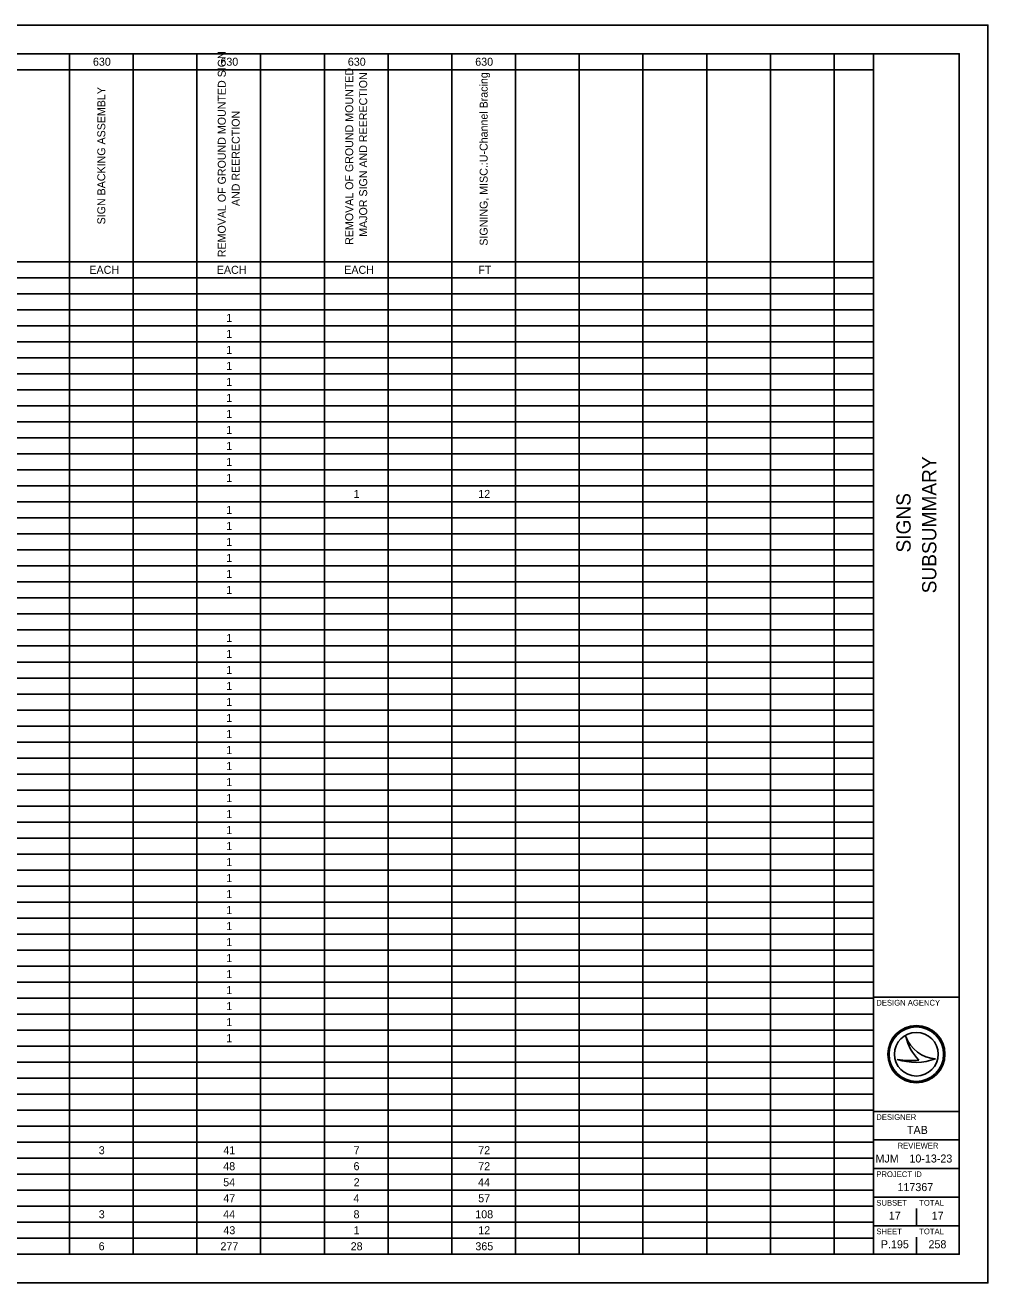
# Model space of a CAD drawing. Extents: x 0 to 34, y 0 to 22.
# Drawn here: x 17.16 to 34, y 0 to 22 of the extents above; entities that cross this region are included whole.
import ezdxf

# ---------------------------------------------------------------- set-up
doc = ezdxf.new("R2010")
doc.units = 0
for name, color, linetype in [('Default', 7, 'Continuous'), ('SH_Border', 7, 'Continuous'), ('SH_Cut_Line', 7, 'Continuous'), ('SH_Data', 7, 'Continuous')]:
    doc.layers.add(name, color=color, linetype=linetype)

msp = doc.modelspace()

# ---------------------------------------------------------------- linework, layer by layer
at = {"layer": 'Default'}
for p, q in [((1.5, 21.5), (32, 21.5)), ((17.938, 21.5), (17.938, 0.5)), ((19.053, 21.5), (19.053, 0.5)), ((20.167, 21.5), (20.167, 0.5)), ((21.282, 21.5), (21.282, 0.5)), ((22.396, 21.5), (22.396, 0.5)), ((23.51, 21.5), (23.51, 0.5)), ((24.625, 21.5), (24.625, 0.5)), ((25.739, 21.5), (25.739, 0.5)), ((26.854, 21.5), (26.854, 0.5)), ((27.968, 21.5), (27.968, 0.5)), ((29.083, 21.5), (29.083, 0.5)), ((30.197, 21.5), (30.197, 0.5)), ((31.312, 21.5), (31.312, 0.5)), ((32, 21.5), (32, 0.5)), ((8.646, 21.22), (32, 21.22)), ((8.646, 17.86), (32, 17.86)), ((1.5, 17.58), (32, 17.58)), ((1.5, 17.3), (32, 17.3)), ((1.5, 17.02), (32, 17.02)), ((1.5, 16.74), (32, 16.74)), ((1.5, 16.46), (32, 16.46)), ((1.5, 16.18), (32, 16.18)), ((1.5, 15.9), (32, 15.9)), ((1.5, 15.62), (32, 15.62)), ((1.5, 15.34), (32, 15.34)), ((1.5, 15.06), (32, 15.06)), ((1.5, 14.78), (32, 14.78)), ((1.5, 14.5), (32, 14.5)), ((1.5, 14.22), (32, 14.22)), ((1.5, 13.94), (32, 13.94)), ((1.5, 13.66), (32, 13.66)), ((1.5, 13.38), (32, 13.38)), ((1.5, 13.1), (32, 13.1)), ((1.5, 12.82), (32, 12.82)), ((1.5, 12.54), (32, 12.54)), ((1.5, 12.26), (32, 12.26)), ((1.5, 11.98), (32, 11.98)), ((1.5, 11.7), (32, 11.7)), ((1.5, 11.42), (32, 11.42)), ((1.5, 11.14), (32, 11.14)), ((1.5, 10.86), (32, 10.86)), ((1.5, 10.58), (32, 10.58)), ((1.5, 10.3), (32, 10.3)), ((1.5, 10.02), (32, 10.02)), ((1.5, 9.74), (32, 9.74)), ((1.5, 9.46), (32, 9.46)), ((1.5, 9.18), (32, 9.18)), ((1.5, 8.9), (32, 8.9)), ((1.5, 8.62), (32, 8.62)), ((1.5, 8.34), (32, 8.34)), ((1.5, 8.06), (32, 8.06)), ((1.5, 7.78), (32, 7.78)), ((1.5, 7.5), (32, 7.5)), ((1.5, 7.22), (32, 7.22)), ((1.5, 6.94), (32, 6.94)), ((1.5, 6.66), (32, 6.66)), ((1.5, 6.38), (32, 6.38)), ((1.5, 6.1), (32, 6.1)), ((1.5, 5.82), (32, 5.82)), ((1.5, 5.54), (32, 5.54)), ((1.5, 5.26), (32, 5.26)), ((1.5, 4.98), (32, 4.98)), ((1.5, 4.7), (32, 4.7)), ((1.5, 4.42), (32, 4.42)), ((1.5, 4.14), (32, 4.14)), ((1.5, 3.86), (32, 3.86)), ((1.5, 3.58), (32, 3.58)), ((1.5, 3.3), (32, 3.3)), ((1.5, 3.02), (32, 3.02)), ((1.5, 2.74), (32, 2.74)), ((1.5, 2.46), (32, 2.46)), ((1.5, 2.18), (32, 2.18)), ((1.5, 1.9), (32, 1.9)), ((1.5, 1.62), (32, 1.62)), ((1.5, 1.34), (32, 1.34)), ((1.5, 1.06), (32, 1.06)), ((1.5, 0.78), (32, 0.78)), ((1.5, 0.5), (32, 0.5))]:
    msp.add_line(p, q, dxfattribs=at)
at = {"layer": 'SH_Border'}
for p, q in [((32, 0.5), (32, 21.5)), ((32, 5), (33.5, 5)), ((32, 3), (33.5, 3)), ((32, 2.5), (33.5, 2.5)), ((32, 2), (33.5, 2)), ((32, 1.5), (33.5, 1.5)), ((32, 1), (33.5, 1))]:
    msp.add_line(p, q, dxfattribs=at)
msp.add_lwpolyline([(1.5, 21.5), (33.5, 21.5), (33.5, 0.5), (1.5, 0.5)], close=True, dxfattribs=at)
at = {"layer": 'SH_Cut_Line'}
msp.add_lwpolyline([(0, 0), (34, 0), (34, 22), (0, 22)], close=True, dxfattribs=at)
at = {"layer": 'SH_Data'}
for p, q in [((32.567, 4.31), (32.567, 4.31)), ((32.75, 4), (32.75, 4)), ((32.417, 3.91), (32.417, 3.91)), ((33.087, 3.919), (33.087, 3.919)), ((32.75, 1), (32.75, 1.3)), ((32.375, 0.675), (32.375, 0.675)), ((32.75, 0.5), (32.75, 0.8))]:
    msp.add_line(p, q, dxfattribs=at)
for radius in [0.5, 0.477, 0.477, 0.382]:
    msp.add_circle((32.75, 4), radius, dxfattribs=at)
for centre, radius, start, end in [((33.116, 4.498), 0.58, 198.9257, 198.9319), ((33.347, 4.47), 0.796, 191.6379, 191.6421), ((33.116, 4.498), 0.58, 198.9319, 267.1657), ((33.347, 4.47), 0.796, 191.6421, 226.0947), ((32.739, 4.87), 1.013, 251.4576, 290.0832), ((32.648, 5.154), 1.266, 259.4964, 259.4995), ((32.739, 4.87), 1.013, 251.4527, 251.4576), ((32.648, 5.154), 1.266, 259.4995, 276.6672)]:
    msp.add_arc(centre, radius, start, end, dxfattribs=at)

# ---------------------------------------------------------------- texts
at = {"layer": 'Default'}
for s, p in [('630', (18.349, 21.29)), ('630', (20.578, 21.29)), ('630', (22.807, 21.29)), ('630', (25.035, 21.29)), ('EACH', (18.286, 17.65)), ('EACH', (20.515, 17.65)), ('EACH', (22.744, 17.65)), ('FT', (25.089, 17.65)), ('1', (20.68, 16.81)), ('1', (20.68, 16.53)), ('1', (20.68, 16.25)), ('1', (20.68, 15.97)), ('1', (20.68, 15.69)), ('1', (20.68, 15.41)), ('1', (20.68, 15.13)), ('1', (20.68, 14.85)), ('1', (20.68, 14.57)), ('1', (20.68, 14.29)), ('1', (20.68, 14.01)), ('1', (22.909, 13.73)), ('12', (25.088, 13.73)), ('1', (20.68, 13.45)), ('1', (20.68, 13.17)), ('1', (20.68, 12.89)), ('1', (20.68, 12.61)), ('1', (20.68, 12.33)), ('1', (20.68, 12.05)), ('1', (20.68, 11.21)), ('1', (20.68, 10.93)), ('1', (20.68, 10.65)), ('1', (20.68, 10.37)), ('1', (20.68, 10.09)), ('1', (20.68, 9.81)), ('1', (20.68, 9.53)), ('1', (20.68, 9.25)), ('1', (20.68, 8.97)), ('1', (20.68, 8.69)), ('1', (20.68, 8.41)), ('1', (20.68, 8.13)), ('1', (20.68, 7.85)), ('1', (20.68, 7.57)), ('1', (20.68, 7.29)), ('1', (20.68, 7.01)), ('1', (20.68, 6.73)), ('1', (20.68, 6.45)), ('1', (20.68, 6.17)), ('1', (20.68, 5.89)), ('1', (20.68, 5.61)), ('1', (20.68, 5.33)), ('1', (20.68, 5.05)), ('1', (20.68, 4.77)), ('1', (20.68, 4.49)), ('1', (20.68, 4.21)), ('3', (18.451, 2.25)), ('41', (20.63, 2.25)), ('7', (22.908, 2.25)), ('72', (25.088, 2.25)), ('48', (20.628, 1.97)), ('6', (22.907, 1.97)), ('72', (25.088, 1.97)), ('54', (20.627, 1.69)), ('2', (22.909, 1.69)), ('44', (25.085, 1.69)), ('47', (20.629, 1.41)), ('4', (22.906, 1.41)), ('57', (25.087, 1.41)), ('3', (18.451, 1.13)), ('44', (20.627, 1.13)), ('8', (22.907, 1.13)), ('108', (25.036, 1.13)), ('43', (20.63, 0.85)), ('1', (22.909, 0.85)), ('12', (25.088, 0.85)), ('6', (18.449, 0.57)), ('277', (20.579, 0.57)), ('28', (22.857, 0.57)), ('365', (25.038, 0.57))]:
    msp.add_text(s, height=0.14, dxfattribs=at).set_placement(p)
for s, p in [('REMOVAL OF GROUND MOUNTED SIGN ', (20.672, 17.941)), ('REMOVAL OF GROUND MOUNTED ', (22.901, 18.157)), ('MAJOR SIGN AND REERECTION', (23.145, 18.298)), ('SIGNING, MISC.:U-Channel Bracing', (25.252, 18.143)), ('SIGN BACKING ASSEMBLY', (18.565, 18.515)), ('AND REERECTION', (20.916, 18.835))]:
    msp.add_text(s, height=0.13931, rotation=90, dxfattribs=at).set_placement(p)
at = {"layer": 'SH_Data'}
for s, p in [('SUBSUMMARY', (33.1, 12.061)), ('SIGNS', (32.65, 12.775))]:
    msp.add_text(s, height=0.25, rotation=90, dxfattribs=at).set_placement(p)
for s, height, p in [('DESIGN AGENCY', 0.1, (32.05, 4.85)), ('DESIGNER', 0.1, (32.05, 2.85)), ('TAB', 0.14, (32.586, 2.605)), ('REVIEWER', 0.1, (32.422, 2.35)), ('MJM', 0.14, (32.035, 2.105)), ('10-13-23', 0.14, (32.629, 2.105)), ('PROJECT ID', 0.1, (32.05, 1.85)), ('117367', 0.14, (32.42, 1.605)), ('SUBSET', 0.1, (32.05, 1.35)), ('TOTAL', 0.1, (32.8, 1.35)), ('17', 0.14, (32.268, 1.105)), ('17', 0.14, (33.018, 1.105)), ('SHEET', 0.1, (32.05, 0.85)), ('TOTAL', 0.1, (32.8, 0.85)), ('P.195', 0.14, (32.129, 0.605)), ('258', 0.14, (32.962, 0.605))]:
    msp.add_text(s, height=height, dxfattribs=at).set_placement(p)

doc.saveas('drawing.dxf')
